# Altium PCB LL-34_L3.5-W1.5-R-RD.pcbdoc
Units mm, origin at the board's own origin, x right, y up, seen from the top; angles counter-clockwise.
Board outline 17.67 x 14.3 mm, 2 copper layers (Top Layer, Bottom Layer), stack 0 mm thick; 1 components, 0 nets, 2 pads, 0 vias.
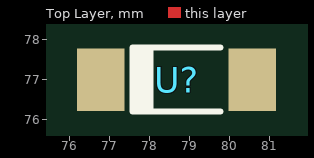
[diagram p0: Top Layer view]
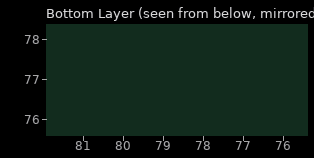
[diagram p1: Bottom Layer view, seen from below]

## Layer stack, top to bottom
Top Layer: signal copper (thickness not stored)
Bottom Layer: signal copper (thickness not stored)

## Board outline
87.52,69.85 69.85,69.85 69.85,84.152 87.52,84.152

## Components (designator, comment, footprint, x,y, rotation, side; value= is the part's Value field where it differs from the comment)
U? "" LL-34_L3.5-W1.5-R-RD 78.685,77.001 r0 top

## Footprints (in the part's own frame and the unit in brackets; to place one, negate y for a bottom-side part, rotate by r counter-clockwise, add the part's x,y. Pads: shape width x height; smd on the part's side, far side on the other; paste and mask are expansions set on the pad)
LL-34_L3.5-W1.5-R-RD [mm]
  rect 1.185x1.566 smd: 1(1.893,0) 2(-1.893,0)
  silkscreen extent -1.1,-0.8 1.1,0.8

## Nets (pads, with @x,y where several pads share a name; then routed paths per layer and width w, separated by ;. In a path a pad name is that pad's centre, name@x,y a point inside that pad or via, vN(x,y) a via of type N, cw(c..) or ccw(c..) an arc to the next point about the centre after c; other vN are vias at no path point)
pads on no net: U?.1 U?.2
